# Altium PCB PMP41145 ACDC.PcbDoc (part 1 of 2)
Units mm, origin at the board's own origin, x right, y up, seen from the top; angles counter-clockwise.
Board outline 48.82 x 27.36 mm, 2 copper layers (Top Layer, Bottom Layer), stack 1.016 mm thick; 61 components, 40 nets, 174 pads, 389 vias.
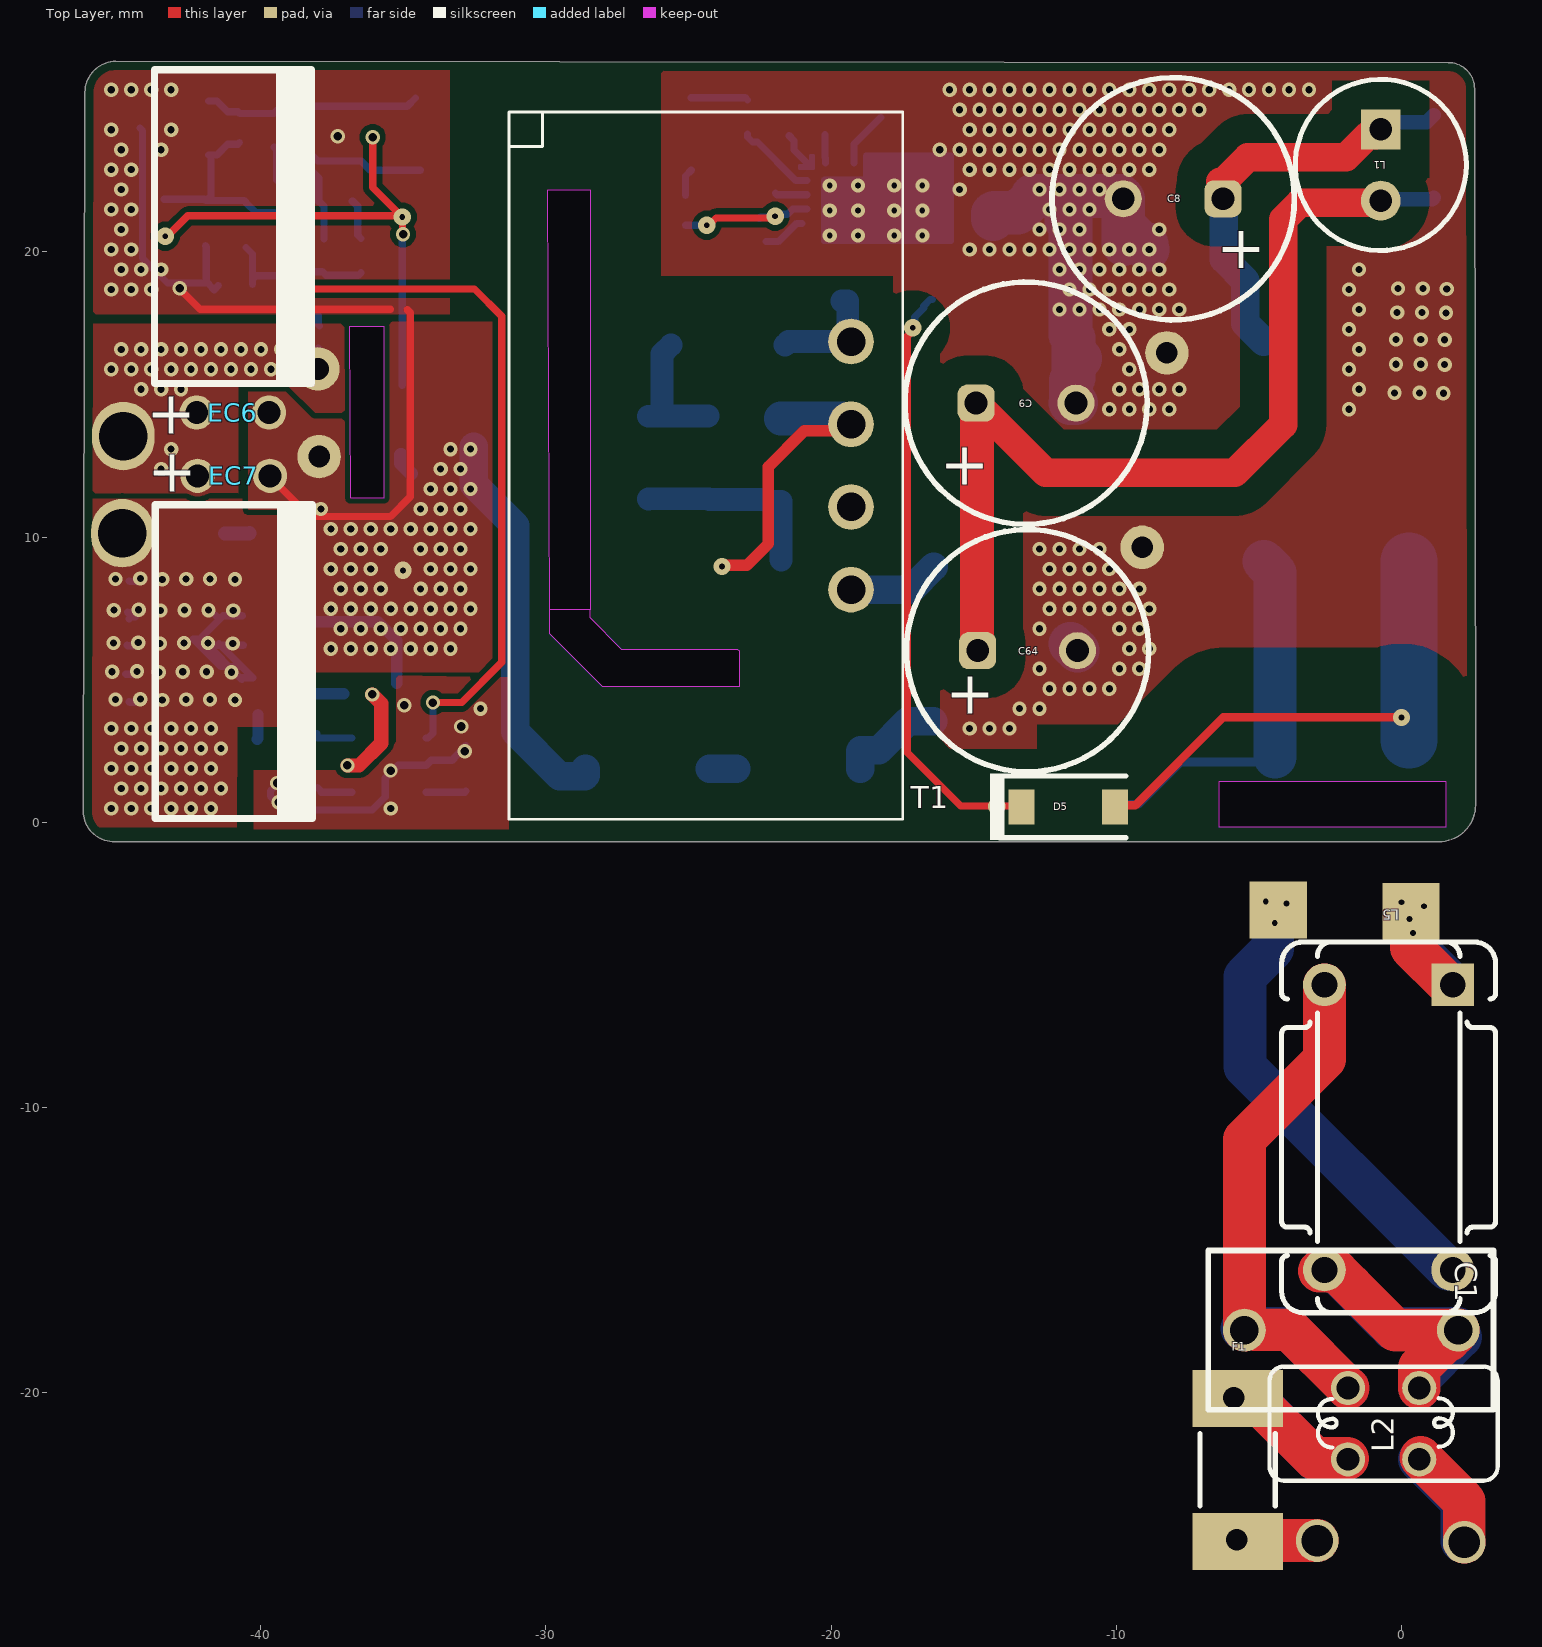
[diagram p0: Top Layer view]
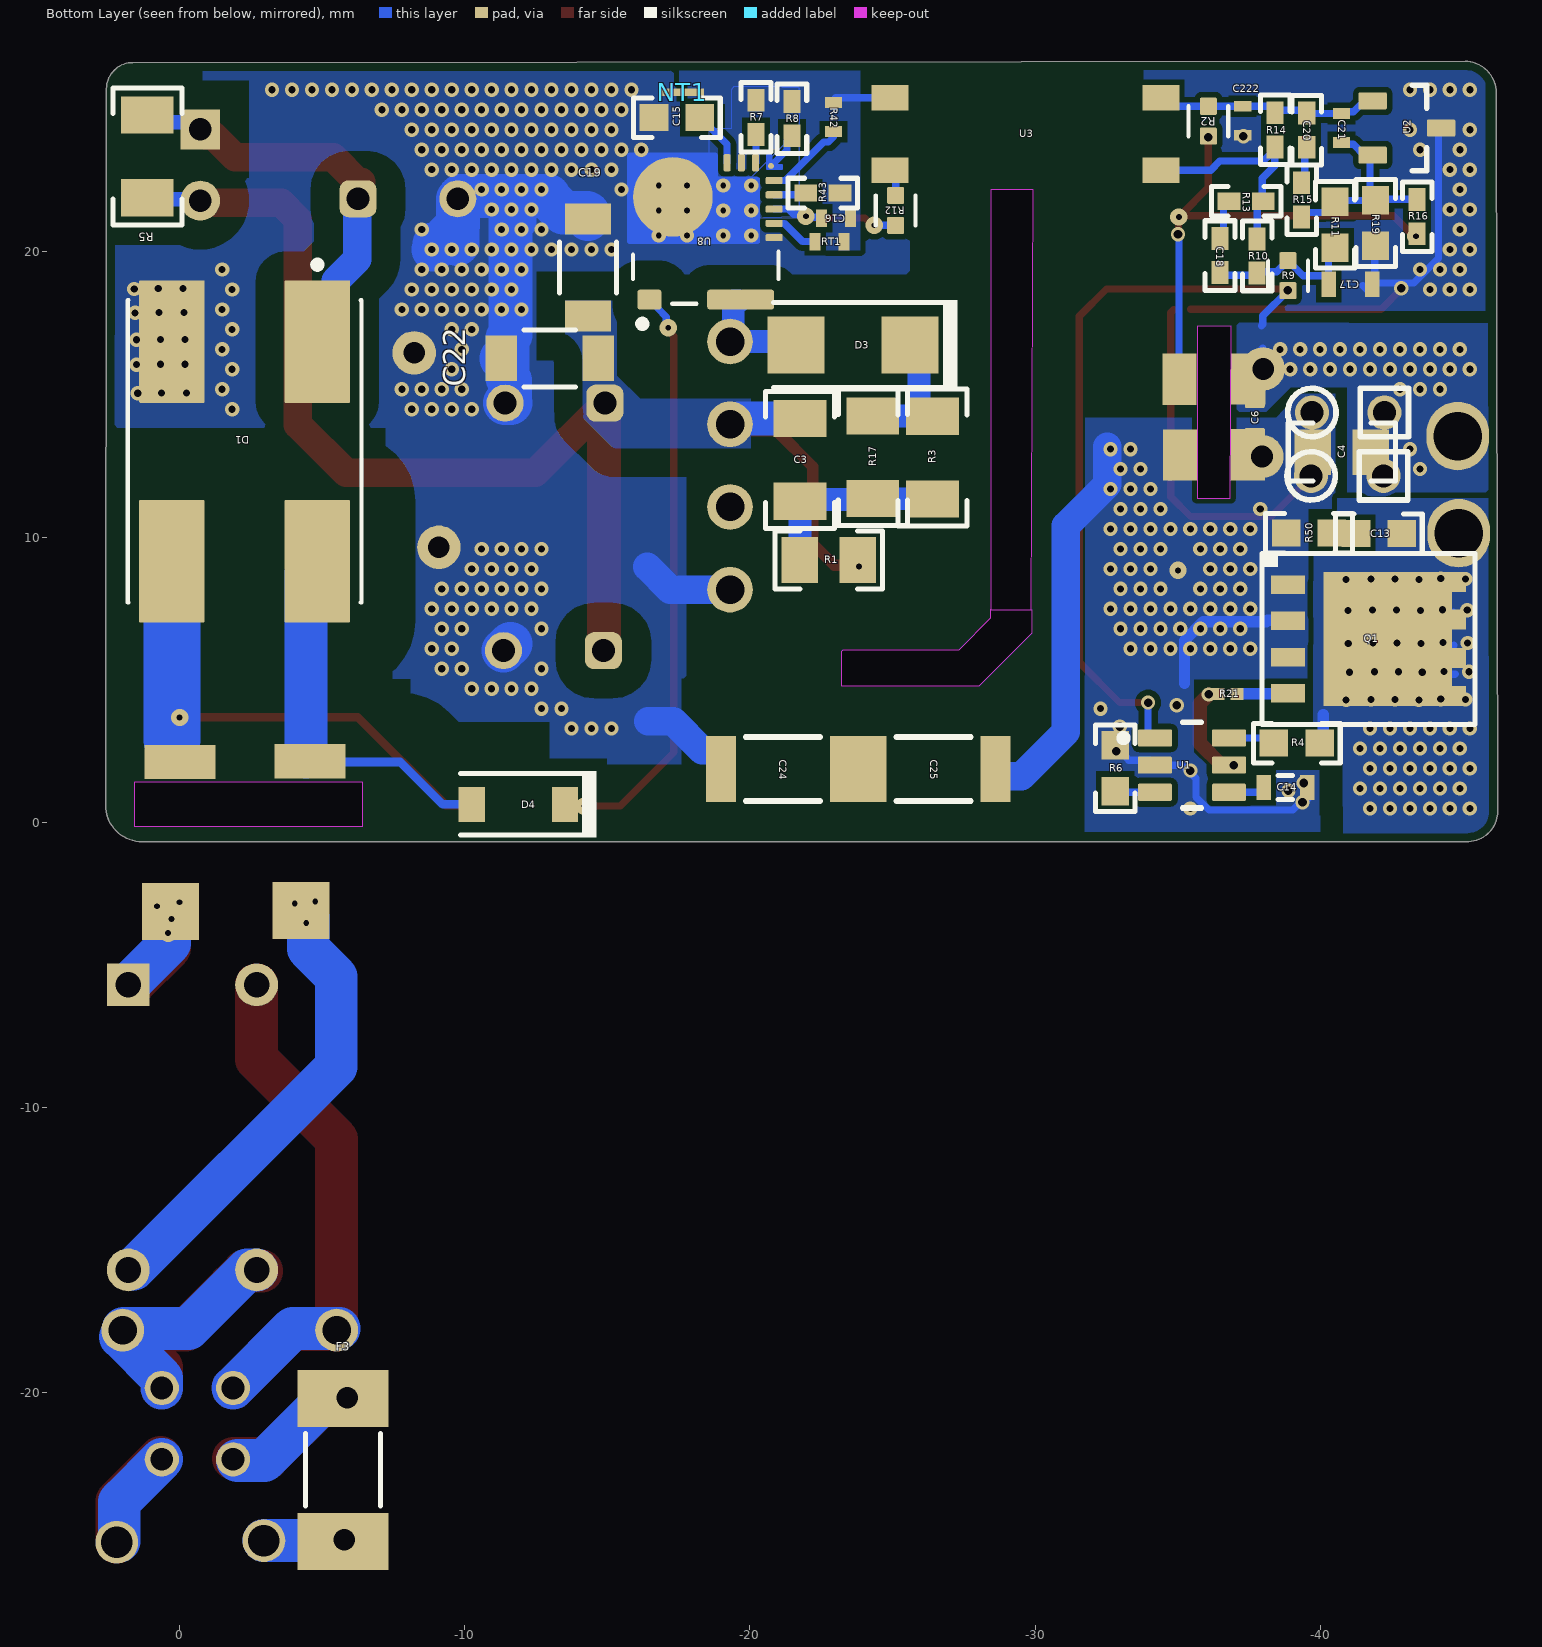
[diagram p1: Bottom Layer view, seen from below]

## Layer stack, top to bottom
Top Solder: solder mask 0.0102, Solder Resist, Dk 3.5
Top Layer: signal copper 0.0711
Dielectric1: core 0.8738, FR-4 High Tg, Dk 4.8
Bottom Layer: signal copper 0.0711
Bottom Solder: solder mask 0.0102, Solder Resist, Dk 3.5

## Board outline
-45.202,-0.676 cw(c-45.155,0.387) -46.208,0.234 -46.219,0.27 -46.164,25.595 cw(c-45.075,25.595) -45.075,26.684 1.643,26.644 cw(c1.643,25.723) 2.564,25.723 2.599,0.602 cw(c1.317,0.602) 1.318,-0.679 1.29,-0.679
cut-out: -6.406,1.425 -6.406,-0.15 1.576,-0.15 1.576,1.425
cut-out: -29.885,7.455 -29.885,6.63 -28.025,4.77 -23.21,4.77 -23.21,6 -23.27,6.06 -27.335,6.06 -28.445,7.17 -28.445,7.47
cut-out: -35.685,11.37 -36.846,11.37 -36.872,17.4 -35.685,17.4
cut-out: -28.445,7.455 -29.869,7.455 -29.931,22.185 -28.445,22.185 -28.445,19.53

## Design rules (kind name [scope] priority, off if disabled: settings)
AcuteAngle [All] p1: minimum=4.50000000000000E+0001 checktracksonly=FALSE
AssemblyTestPointUsage [All] p1: valid=2
BoardOutlineClearance BoardOutlineClearance_MountingHoles [OnCopper and InComponentClass('Mounting Holes')] p1: gap=0.3 ignorepadtopadclearanceinfootprint=FALSE
BoardOutlineClearance BoardOutlineClearance_Poly [OnCopper and IsPoly] p2: gap=0.3 ignorepadtopadclearanceinfootprint=FALSE
BoardOutlineClearance [OnCopper and Not InComponentClass('Logo') and not InComponentClass('FiducialMark') and not InRegion(1000,500,4000,800) and not InPoly] p3: gap=0.3 ignorepadtopadclearanceinfootprint=FALSE
Clearance Clearance_VAC_PGND [InNetClass('VAC') vs InNetClass('PGND')] p1: gap=2.286 ignorepadtopadclearanceinfootprint=TRUE
Clearance Clearance_HV_PGND [InNetClass('High Voltage') vs InNetClass('PGND')] p2: gap=1.016 ignorepadtopadclearanceinfootprint=TRUE
Clearance Clearance_SW_PGND [InNetClass('Switch Node') vs InNetClass('PGND')] p3: gap=0.864 ignorepadtopadclearanceinfootprint=TRUE
Clearance Clearance_AC_AC [InNetClass('VAC') vs InNetClass('VAC')] p4: gap=1 ignorepadtopadclearanceinfootprint=TRUE
Clearance Clearance_PGND_SGND [InNetClass('PGND') vs InNetClass('SGND')] p5: gap=4.064 ignorepadtopadclearanceinfootprint=TRUE
Clearance Clearance_HV_LV [InNetClass('High Voltage') vs InNetClass('Low Voltage')] p6: gap=0.864 ignorepadtopadclearanceinfootprint=TRUE
Clearance Clearance_SW_LV_1 [InNetClass('Switch Node') vs InNetClass('Low Voltage')] p7: gap=0.864 ignorepadtopadclearanceinfootprint=TRUE
Clearance Clearance_SW_HV [InNetClass('Switch Node') vs InNetClass('High Voltage')] p8: gap=0.864 ignorepadtopadclearanceinfootprint=TRUE
Clearance Clearance_1 [All] p9: gap=0.198 ignorepadtopadclearanceinfootprint=TRUE
Clearance Clearance_Keepouts [((IsTrack Or IsArc) And Not InPoly) And IsFree and IsKeepOut vs ((IsTrack Or IsArc) And Not InPoly) And IsFree and IsKeepOut] p10: gap=0 ignorepadtopadclearanceinfootprint=FALSE
Clearance Clearance_Poly [InPolygon] p11: gap=0.254 ignorepadtopadclearanceinfootprint=TRUE
Clearance Clearance_FiducialMark [IsKeepOut and InComponentClass('FiducialMark') vs IsPad and InComponentClass('FiducialMark')] p12: gap=0 ignorepadtopadclearanceinfootprint=FALSE
ComponentClearance ComponentClearance_MountingHoles_FiducialMarks [InComponentClass('Mounting Holes') vs InComponentClass('FiducialMark')] p1: gap=0.2 collisioncheckmode=3 verticalgap=0.2 showdistances=FALSE
ComponentClearance ComponentClearance_Shunt [InComponentClass('Header') vs InComponentClass('Shunt')] p2: gap=0 collisioncheckmode=3 verticalgap=0 showdistances=FALSE
ComponentClearance ComponentClearance_Logo [InComponentClass('Logo')] p3: gap=0.2 collisioncheckmode=3 verticalgap=0.2 showdistances=FALSE
ComponentClearance ComponentClearance_ScrewToNut [(HasFootprint('NY PMS 440 0025 PH')) vs (HasFootprint('Keystone_1902C'))] p4: gap=0.127 collisioncheckmode=3 verticalgap=0.254 showdistances=FALSE
ComponentClearance ComponentClearance_MountingHoles [InComponentClass('Mounting Holes')] p5: gap=1 collisioncheckmode=3 verticalgap=2540 showdistances=FALSE
ComponentClearance ComponentClearance_SmallPassives [HasFootprint('0201*') or HasFootprint('0402*') or HasFootprint('0508') or HasFootprint('0603*') or HasFootprint('0612') or HasFootprint('0805*') or HasFootprint('0815*') or HasFootprint('0830*') or HasFootprint('1206*') or HasFootprint('1210*') or HasFootprint('1808*') or HasFootprint('1812*') or HasFootprint('1825*') or HasFootprint('2010*') or HasFootprint('2220*') or HasFootprint('2225*') or HasFootprint('2512*') or HasFootprint('2728*') or HasFootprint('3518*') vs HasFootprint('0201*') or HasFootprint('0402*') or HasFootprint('0508') or HasFootprint('0603*') or HasFootprint('0612') or HasFootprint('0805*') or HasFootprint('0815*') or HasFootprint('0830*') or HasFootprint('1206*') or HasFootprint('1210*') or HasFootprint('1808*') or HasFootprint('1812*') or HasFootprint('1825*') or HasFootprint('2010*') or HasFootprint('2220*') or HasFootprint('2225*') or HasFootprint('2512*') or HasFootprint('2728*') or HasFootprint('3518*')] p6: gap=0.2 collisioncheckmode=3 verticalgap=0.2 showdistances=FALSE
ComponentClearance ComponentClearance_THtoSMT [IsThruComponent vs IsSMTComponent] p7: gap=0.2 collisioncheckmode=3 verticalgap=0.2 showdistances=FALSE
ComponentClearance ComponentClearance_THtoTH [IsThruComponent vs IsThruComponent] p8: gap=0.2 collisioncheckmode=3 verticalgap=0.2 showdistances=FALSE
ComponentClearance [All] p9: gap=0.1 collisioncheckmode=3 verticalgap=0.1 showdistances=FALSE
DiffPairsRouting DiffPair_DiffPairsRouting [All] p1: maxlimit=0.254 minlimit=0.254 mostfreqgap=0.254 toplayer_minwidth=0.254 toplayer_maxwidth=0.254 toplayer_prefwidth=0.254 bottomlayer_minwidth=0.254 bottomlayer_maxwidth=0.254 bottomlayer_prefwidth=0.254 filterlayerstackid={9F2BDCAB-BF4A-4FAE-9F57-695CEC5DA6CF} maxuncoupledlength=12.7
DiffPairsRouting DiffPair_DiffPairsRouting_1 [InDifferentialPair ('NewDifferentialPair1')] p2: maxlimit=0.203 minlimit=0.203 mostfreqgap=0.203 toplayer_minwidth=0.254 toplayer_maxwidth=0.254 toplayer_prefwidth=0.254 bottomlayer_minwidth=0.254 bottomlayer_maxwidth=0.254 bottomlayer_prefwidth=0.254 filterlayerstackid={9F2BDCAB-BF4A-4FAE-9F57-695CEC5DA6CF} maxuncoupledlength=12.7
DiffPairsRouting DiffPair_DiffPairsRouting_2 [InDifferentialPair ('NewDifferentialPair1')] p3: maxlimit=0.127 minlimit=0.127 mostfreqgap=0.127 toplayer_minwidth=0.254 toplayer_maxwidth=0.254 toplayer_prefwidth=0.254 bottomlayer_minwidth=0.254 bottomlayer_maxwidth=0.254 bottomlayer_prefwidth=0.254 filterlayerstackid={9F2BDCAB-BF4A-4FAE-9F57-695CEC5DA6CF} maxuncoupledlength=12.7
DiffPairsRouting DiffPair_DiffPairsRouting_3 [InDifferentialPair ('NewDifferentialPair1')] p4: maxlimit=0.178 minlimit=0.178 mostfreqgap=0.178 toplayer_minwidth=0.254 toplayer_maxwidth=0.254 toplayer_prefwidth=0.254 bottomlayer_minwidth=0.254 bottomlayer_maxwidth=0.254 bottomlayer_prefwidth=0.254 filterlayerstackid={9F2BDCAB-BF4A-4FAE-9F57-695CEC5DA6CF} maxuncoupledlength=12.7
DiffPairsRouting DiffPair_DiffPairsRouting_4 [InDifferentialPair ('NewDifferentialPair1')] p5: maxlimit=0.254 minlimit=0.254 mostfreqgap=0.254 toplayer_minwidth=0.381 toplayer_maxwidth=0.381 toplayer_prefwidth=0.381 bottomlayer_minwidth=0.381 bottomlayer_maxwidth=0.381 bottomlayer_prefwidth=0.381 filterlayerstackid={9F2BDCAB-BF4A-4FAE-9F57-695CEC5DA6CF} maxuncoupledlength=12.7
DiffPairsRouting DiffPair_DiffPairsRouting_5 [All] p6: maxlimit=0.254 minlimit=0.254 mostfreqgap=0.254 toplayer_minwidth=0.254 toplayer_maxwidth=0.254 toplayer_prefwidth=0.254 bottomlayer_minwidth=0.254 bottomlayer_maxwidth=0.254 bottomlayer_prefwidth=0.254 filterlayerstackid={9F2BDCAB-BF4A-4FAE-9F57-695CEC5DA6CF} maxuncoupledlength=12.7
DiffPairsRouting DiffPair_DiffPairsRouting_6 [All] p7: maxlimit=0.254 minlimit=0.254 mostfreqgap=0.254 toplayer_minwidth=0.254 toplayer_maxwidth=0.254 toplayer_prefwidth=0.254 bottomlayer_minwidth=0.254 bottomlayer_maxwidth=0.254 bottomlayer_prefwidth=0.254 filterlayerstackid={9F2BDCAB-BF4A-4FAE-9F57-695CEC5DA6CF} maxuncoupledlength=12.7
DiffPairsRouting DiffPair_DiffPairsRouting_7 [InDifferentialPair ('NewDifferentialPair2')] p8: maxlimit=0.254 minlimit=0.254 mostfreqgap=0.254 toplayer_minwidth=0.254 toplayer_maxwidth=0.254 toplayer_prefwidth=0.254 bottomlayer_minwidth=0.254 bottomlayer_maxwidth=0.254 bottomlayer_prefwidth=0.254 filterlayerstackid={9F2BDCAB-BF4A-4FAE-9F57-695CEC5DA6CF} maxuncoupledlength=12.7
DiffPairsRouting DiffPair_DiffPairsRouting_8 [InDifferentialPair ('NewDifferentialPair2')] p9: maxlimit=0.254 minlimit=0.254 mostfreqgap=0.254 toplayer_minwidth=0.381 toplayer_maxwidth=0.381 toplayer_prefwidth=0.381 bottomlayer_minwidth=0.381 bottomlayer_maxwidth=0.381 bottomlayer_prefwidth=0.381 filterlayerstackid={9F2BDCAB-BF4A-4FAE-9F57-695CEC5DA6CF} maxuncoupledlength=12.7
DiffPairsRouting DiffPair_DiffPairsRouting_9 [InDifferentialPair ('ISense_A')] p10: maxlimit=0.198 minlimit=0.198 mostfreqgap=0.198 toplayer_minwidth=0.254 toplayer_maxwidth=0.254 toplayer_prefwidth=0.254 bottomlayer_minwidth=0.254 bottomlayer_maxwidth=0.254 bottomlayer_prefwidth=0.254 filterlayerstackid={9F2BDCAB-BF4A-4FAE-9F57-695CEC5DA6CF} maxuncoupledlength=12.7
DiffPairsRouting DiffPair_DiffPairsRouting_10 [InDifferentialPair ('ISense_A')] p11: maxlimit=0.254 minlimit=0.254 mostfreqgap=0.254 toplayer_minwidth=0.381 toplayer_maxwidth=0.381 toplayer_prefwidth=0.381 bottomlayer_minwidth=0.381 bottomlayer_maxwidth=0.381 bottomlayer_prefwidth=0.381 filterlayerstackid={9F2BDCAB-BF4A-4FAE-9F57-695CEC5DA6CF} maxuncoupledlength=12.7
DiffPairsRouting DiffPair_DiffPairsRouting_11 [InDifferentialPair ('ISense_A')] p12: maxlimit=0.254 minlimit=0.254 mostfreqgap=0.254 toplayer_minwidth=0.381 toplayer_maxwidth=0.381 toplayer_prefwidth=0.381 bottomlayer_minwidth=0.381 bottomlayer_maxwidth=0.381 bottomlayer_prefwidth=0.381 filterlayerstackid={9F2BDCAB-BF4A-4FAE-9F57-695CEC5DA6CF} maxuncoupledlength=12.7
DiffPairsRouting DiffPair_ADiffPairsRouting [All] p13: maxlimit=0.198 minlimit=0.198 mostfreqgap=0.198 toplayer_minwidth=0.254 toplayer_maxwidth=0.254 toplayer_prefwidth=0.254 bottomlayer_minwidth=0.254 bottomlayer_maxwidth=0.254 bottomlayer_prefwidth=0.254 filterlayerstackid={9F2BDCAB-BF4A-4FAE-9F57-695CEC5DA6CF} maxuncoupledlength=12.7
DiffPairsRouting [All] p14: maxlimit=2.54 minlimit=0.254 mostfreqgap=0.254 toplayer_minwidth=0.381 toplayer_maxwidth=0.381 toplayer_prefwidth=0.381 bottomlayer_minwidth=0.381 bottomlayer_maxwidth=0.381 bottomlayer_prefwidth=0.381 maxuncoupledlength=25.4
FabricationTestPointUsage TestPointUsage [All] p1: valid=2 allowmultiple=FALSE
FabricationTestpoint Testpoint [All] p1: side=3 testpointundercomponent=TRUE minsize=1.016 maxsize=2.54 preferedsize=1.524 minholesize=0 maxholesize=1.016 preferedholesize=0.813 testpointgrid=0.025 allowsidetop=TRUE allowsidebottom=TRUE usegrid=TRUE gridtolerance=0
FanoutControl Fanout_LCC [IsLCC] p1: bgadir=Out bgaviamode=Centered fanoutstyle=Auto fanoutdirection=Alternating viagrid=0.025 // Fanout_LCC (Default Rule)
FanoutControl Fanout_BGA [IsBGA] p2: bgadir=Out bgaviamode=Centered fanoutstyle=Auto fanoutdirection=Alternating viagrid=0.025 // Fanout_BGA (Default Rule)
HoleSize [All] p1: absolutevalues=TRUE maxlimit=6.375 minlimit=0.2 maxpercent=80.000 minpercent=20.000
MatchedLengths DiffPair_MatchedLengths [All] p1: tolerance=25.4 checknetsindiffpair=FALSE checkdiffpairvsdiffpair=TRUE checkxsignals=TRUE checkothers=TRUE
MatchedLengths DiffPair_MatchedLengths_1 [InDifferentialPair ('NewDifferentialPair1')] p2: tolerance=25.4 checknetsindiffpair=FALSE checkdiffpairvsdiffpair=TRUE checkxsignals=TRUE checkothers=TRUE
MatchedLengths DiffPair_MatchedLengths_2 [InDifferentialPair ('NewDifferentialPair1')] p3: tolerance=25.4 checknetsindiffpair=FALSE checkdiffpairvsdiffpair=TRUE checkxsignals=TRUE checkothers=TRUE
MatchedLengths DiffPair_MatchedLengths_3 [InDifferentialPair ('NewDifferentialPair1')] p4: tolerance=25.4 checknetsindiffpair=FALSE checkdiffpairvsdiffpair=TRUE checkxsignals=TRUE checkothers=TRUE
MatchedLengths DiffPair_MatchedLengths_4 [InDifferentialPair ('NewDifferentialPair1')] p5: tolerance=25.4 checknetsindiffpair=FALSE checkdiffpairvsdiffpair=TRUE checkxsignals=TRUE checkothers=TRUE
MatchedLengths DiffPair_MatchedLengths_5 [All] p6: tolerance=25.4 checknetsindiffpair=FALSE checkdiffpairvsdiffpair=TRUE checkxsignals=TRUE checkothers=TRUE
MatchedLengths DiffPair_MatchedLengths_6 [All] p7: tolerance=25.4 checknetsindiffpair=FALSE checkdiffpairvsdiffpair=TRUE checkxsignals=TRUE checkothers=TRUE
MatchedLengths DiffPair_MatchedLengths_7 [InDifferentialPair ('NewDifferentialPair2')] p8: tolerance=25.4 checknetsindiffpair=FALSE checkdiffpairvsdiffpair=TRUE checkxsignals=TRUE checkothers=TRUE
MatchedLengths DiffPair_MatchedLengths_8 [InDifferentialPair ('NewDifferentialPair2')] p9: tolerance=25.4 checknetsindiffpair=FALSE checkdiffpairvsdiffpair=TRUE checkxsignals=TRUE checkothers=TRUE
MatchedLengths DiffPair_MatchedLengths_9 [InDifferentialPair ('ISense_A')] p10: tolerance=25.4 checknetsindiffpair=FALSE checkdiffpairvsdiffpair=TRUE checkxsignals=TRUE checkothers=TRUE
MatchedLengths DiffPair_MatchedLengths_10 [InDifferentialPair ('ISense_A')] p11: tolerance=25.4 checknetsindiffpair=FALSE checkdiffpairvsdiffpair=TRUE checkxsignals=TRUE checkothers=TRUE
MatchedLengths DiffPair_MatchedLengths_11 [InDifferentialPair ('ISense_A')] p12: tolerance=25.4 checknetsindiffpair=FALSE checkdiffpairvsdiffpair=TRUE checkxsignals=TRUE checkothers=TRUE
MatchedLengths DiffPair_AMatchedLengths [All] p13: tolerance=25.4 checknetsindiffpair=FALSE checkdiffpairvsdiffpair=TRUE checkxsignals=TRUE checkothers=TRUE
MinimumAnnularRing MinimumAnnularRing_ThermalPadVias [IsVia and InAnyComponent] p1: minimumring=0.15
MinimumAnnularRing [All] p2: minimumring=0.2
MinimumSolderMaskSliver MinimumSolderMaskSliver_Logo [InComponentClass('Logo') vs InComponentClass('Logo')] p1: minsoldermaskwidth=0.018
MinimumSolderMaskSliver [All] p2: minsoldermaskwidth=0.1
PlaneConnect [All] p1: planeconnectstyle=Relief reliefexpansion=0.254 reliefentries=4 reliefconductorwidth=0.254 reliefairgap=0.254
PolygonConnect [All] p1: connectstyle=Direct reliefconductorwidth=0.254 reliefentries=4 polygonreliefangle="90 Angle" airgapwidth=0
RoutingVias ThermalPadVias [IsVia and InAnyComponent] p1: holewidth=0.2 width=0.5 viastyle="Through Hole" minholewidth=0.2 minwidth=0.5 maxholewidth=0.33 maxwidth=0.6
RoutingVias [All] p2: holewidth=0.406 width=0.864 viastyle="Through Hole" minholewidth=0.2 minwidth=0.61 maxholewidth=1.016 maxwidth=1.651
SilkToSilkClearance SilkToSilkClearance_Pb-FreeLogo [(HasFootprint('Pb-Free_Overlay_Medium') OR HasFootprint('Pb-Free_Overlay_Small')) vs (HasFootprint('Pb-Free_Overlay_Medium') OR HasFootprint('Pb-Free_Overlay_Small'))] p1: silktosilkclearance=0
SilkToSilkClearance [All] p2: silktosilkclearance=0.1
SilkToSolderMaskClearance SilkToComponentPadClearance [(IsPad or IsFill or IsRegion) and InAnycomponent] p1: minsilkscreentomaskgap=0.127 clearancetoexposedcopper=TRUE
SilkToSolderMaskClearance "Silk to Solder Mask Opening" [All] p2: minsilkscreentomaskgap=0.1 clearancetoexposedcopper=FALSE
SolderMaskExpansion [All] p1: expansion=0.05 istentingtop=FALSE
UnRoutedNet [All] p1: checkbadconnections=TRUE
Width [All] p1: maxlimit=2.54 minlimit=0.152 preferedwidth=0.254 checkconnectedcopper=TRUE
17 further rules are at their usual default settings.

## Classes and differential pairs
net class "Low Voltage": APGND FB_ACDC NetC15_1 NetC16_1 NetC17_2 NetC18_2 NetC20_1 NetC20_2 NetC21_1 NetD3_2 NetD4_1 NetR7_2 NetR8_2 NetR10_1 NetR12_2 NetR42_2 NetR43_2 NetRT1_2 NetU2_2 NetU2_8 NetU2_9 NetU2_16 NetU2_17 NetU2_18 NetU2_19 NetU2_20 NetU2_21 NetU7_8 PGND SGND VO_ACDC
net class VAC: LINE NetC1_1 NetC1_2 NetD1_2 NetD1_3 Neture
net class "Switch Node": NetD3_2
net class SGND: SGND VO_ACDC VSR_SW
net class PGND: PGND
net class "High Voltage": NetC3_2 NetC8_1 NetD4_1
component class "ACDC Low Side": C3 C4 C6 C8 C9 C13 C14 C15 C16 C17 C18 C19 C20 C21 C22 C24 C25 C64 C222 D1 D3 D4 D5 EC6 EC7 L1 NT1 Q1 R1 R2 R3 R4 R5 R6 R7 R8 R9 R10 R11 R12 R13 R14 R15 R16 R17 R19 R21 R42 R43 R50 RT1 T1 U1 U2 U3 U8

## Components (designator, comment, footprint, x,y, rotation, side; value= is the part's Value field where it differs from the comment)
C1 "890324023028" "X CAP small form 7_10_8" -5.505,-17.805 r0 top
C3 "GRM31BR72J102KW01L" 1206 -21.758,12.71 r90 bottom value=1000pF
C4 "TMK212BBJ106KG-T" 0805_HV -40.753,12.982 r0 bottom value=10uF
C6 "CGA3E2X8R1E104K080AD" FP-CGA3E2X8R1E104K080AD_0603-MFG -37.701,14.178 r270 bottom value=100nF
C8 "33u/400V" WCAP-ATG5_D8H16 -8.005,21.865 r0 top value=33uF
C9 "33u/400V" WCAP-ATG5_D8H16 -13.163,14.699 r180 top value=33uF
C13 "GRM1885C2A221JA01D" 0603 -42.05,10.125 r0 bottom value=220pF
C14 "CGA3E1X7R1E105K080AC" 0603S -38.771,1.223 r180 bottom value=1uF
C15 "GRM188R61E106KA73D" 0603 -17.435,24.712 r0 bottom value=10uF
C16 "GRM155R71H331KA01D" 0402S -23.018,21.186 r180 bottom value=330pF
C17 "C1608X7R1E105K080AB" 0603S -41.052,18.87 r0 bottom value=1uF
C18 "GRM155R71H183KA12D" 0402 -36.48,19.875 r90 bottom value=0.018uF
C19 "C3216X7T2W104M160AA" 1206_180 -14.32,19.455 r90 bottom value=0.1uF
C20 "GRM155R71H472KA01D" 0402 -39.525,24.27 r90 bottom value=4700pF
C21 "885012205055" 0402S -40.74,24.345 r90 bottom value=100pF
C22 "C3216X7T2W104M160AA" 1206_180 -12.977,16.269 r0 bottom value=0.1uF
C24 "885362210009" WCAP-CSSA_1808_L4.5W2H1.6 -21.156,1.871 r180 bottom value=470pF
C25 "885362210009" WCAP-CSSA_1808_L4.5W2H1.6 -26.436,1.871 r180 bottom value=470pF
C64 "33u/400V" WCAP-ATG5_D8H16 -13.109,6.021 r180 top value=33uF
C222 "885012205055" 0402S -37.275,24.6 r90 bottom value=100pF
D1 "Z4DGP406L-HF" FP-Z4DGP406L-HF_SMT_8MM1_10MM5-MFG -2.28,13.005 r180 bottom
D3 "MRA4007T3G" SMA -23.614,16.74 r0 bottom value=1000V
D4 "ES1JFL" SOD-123 -11.88,0.63 r0 bottom value=600V
D5 "ES1JFL" SOD-123 -11.685,0.54 r0 top value=600V
EC6 "ECAP_LAYDOWN" CE05.5P254L11 -42.245,14.37 r0 top value=470uF
EC7 "ECAP_LAYDOWN" CE05.5P254L11 -42.215,12.15 r0 top value=470uF
F1 "SSQ 3" FUSE_SSQ -5.745,-22.71 r90 top
F3 "SSQ 3" FUSE_SSQ -5.73,-22.71 r90 bottom
L1 "7447462220" WE-TI_5075 -0.725,23.051 r270 top value=22uH
L2 "" L-T8*5 -0.647,-21.088 r180 top
L5 "744821201" WE-CMB_XS -0.45,-10.695 r270 top value=1mH
NT1 "Net-Tie" Net-Tie_10milWide_30milLong -17.621,25.599 r180 bottom net-tie
Q1 "BSC093N15NS5ATMA1" PG-TDSON-8 -41.69,6.43 r180 bottom value=150V
R1 "CRCW0805470KJNEA" 0805_HV -22.763,9.201 r180 bottom value=470k
R2 "CRCW04020000Z0EDHP" FP-CRCW04020000Z0EDHP_0402-MFG -36.075,24.585 r90 bottom value=0
R3 "RC1206FR-0730RL" 1206 -26.401,12.789 r270 bottom value=30.0
R4 "RC0603FR-07300RL" 0603 -39.174,2.777 r0 bottom value=300
R5 "CRCW12064K70JNEA" 1206 1.133,23.352 r270 bottom value=4.7k
R6 "CRCW060347K0FKEA" 0603 -32.807,1.897 r270 bottom value=47.0k
R7 "CRCW040228K7FKED" 0402 -20.21,24.72 r270 bottom value=28.7k
R8 "CRCW040228K7FKED" 0402 -21.47,24.675 r270 bottom value=28.7k
R9 "CRCW04020000Z0EDHP" FP-CRCW04020000Z0EDHP_0402-MFG -38.865,19.17 r270 bottom value=0
R10 "CRCW04023K01FKED" 0402 -37.785,19.86 r270 bottom value=3.01k
R11 "RC0603FR-07232KL" 0603 -40.515,20.955 r270 bottom value=232k
R12 "CRCW04020000Z0EDHP" FP-CRCW04020000Z0EDHP_0402-MFG -25.108,21.457 r90 bottom value=0
R13 "CRCW0402150RFKED" 0402 -37.395,21.78 r0 bottom value=150
R14 "CRCW040215K0FKED" 0402 -38.415,24.285 r270 bottom value=15.0k
R15 "RC0402FR-074K7L" 0402 -39.345,21.825 r270 bottom value=4.70k
R16 "CRCW04021R00JNED" 0402 -43.395,21.24 r270 bottom value=1.0
R17 "RC1206FR-0730RL" 1206 -24.306,12.805 r270 bottom value=30.0
R19 "CRCW060333K0FKEA" 0603 -41.94,21.015 r90 bottom value=33.0k
R21 "CRCW02010000Z0ED" 0201 -36.745,4.505 r0 bottom value=0
R42 "CRCW040275K0FKED" 0402S -22.93,24.728 r270 bottom value=75.0k
R43 "CRCW04025K23FKED" 0402 -22.553,22.065 r0 bottom value=5.23k
R50 "CRCW060312R0JNEA" 0603 -39.6,10.14 r180 bottom value=12
RT1 "NCP15WF104F03RC" 0402S -22.792,20.363 r0 bottom value=100k
T1 "ATQ23_14 4_4 Pin" "ATQ23.9_13.8_REMOVE FLYWIRE" -19.3,12.51 r0 top
U1 "MP6908GJ-Z" FP-MP6908GJ-Z_TSOT23-6-MFG -35.498,2.005 r180 bottom
U2 "ATL431AIDBZR" DBZ0003A_N -43.033,24.346 r180 bottom
U3 "VOL618A-2T" SOP254P1020X230-4 -29.655,24.14 r0 bottom
U8 "UCG28826" REZ0012A-MFG -18.448,20.73 r90 bottom

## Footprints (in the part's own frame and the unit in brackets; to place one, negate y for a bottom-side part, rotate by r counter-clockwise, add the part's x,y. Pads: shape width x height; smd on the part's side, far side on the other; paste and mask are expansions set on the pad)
0201 [mm] "Data from Kemet datasheet CC101_COM dated 7/28/11"
  rect 0.46x0.42 smd mask+0.048: 1(-0.33,0) 2(0.33,0)
  body extent -0.31,-0.16 0.31,0.16, height 0.26
0402 [mm] "0402 from SM-752 data"
  rect 0.8x0.6 smd: 1(-0.6,0) 2(0.6,0)
  silkscreen extent -1.22,-0.52 1.22,0.52, body extent -0.55,-0.3 0.55,0.3, height 0.6
0402S [mil] "Based on C0402S footprint from PADS legacy"
  rect 15x24 smd: 1(-20,0) 2(20,0)
  body extent -22,-12 22,12, height 24
0603 [mm] "0603 from SM-752 data"
  rect 1x0.95 smd: 1(-0.8,0) 2(0.8,0)
  silkscreen extent -1.52,-0.69 1.52,0.69, body extent -0.87,-0.47 0.87,0.47, height 1
0603S [mil]
  rect 20x35 smd: 1(-30,0) 2(30,0)
  silkscreen extent -10,-17 10,17, body extent -34,-19 34,19, height 39
0805_HV [mil] "0805 with 30mil clearance between pads"
  rect 50x63 smd: 1(-40,0) 2(40,0)
  silkscreen extent -74,-40 74,40, body extent -43,-29 43,29, height 57
1206 [mm] "1206 from SM-752 data"
  rect 1.3x1.85 smd: 1(-1.45,0) 2(1.45,0)
  silkscreen extent -2.4,-1.21 2.4,1.21, body extent -1.7,-0.9 1.7,0.9, height 1.35
1206_180 [mm] "1206_180"
  rect 1.1x1.6 smd: 1(-1.7,0) 2(1.7,0)
  silkscreen extent -0.9,-1 0.9,1, body extent -1.75,-0.95 1.75,0.95, height 1.8
"ATQ23.9_13.8_REMOVE FLYWIRE" [mm]
  round 1.6 hole 1: 1(0,-4.35) 2(0,-1.45) 3(0,1.45) 4(0,4.35)
  silkscreen extent -11.99,-12.4 1.81,12.4
CE05.5P254L11 [mm]
  round 1.2 hole 0.8: 1(0,0) 2(2.54,0)
  silkscreen extent -1.48,1.02 4.02,12.02
DBZ0003A_N [mm] "SOT23, 3-Leads, Body 2.9x1.3mm, Pitch 0.95mm, Lead Span 2.4mm, IPC Medium Density"
  rrect17% 1x0.6 smd: 1(-1.2,0.95) 2(-1.2,-0.95) 3(1.2,0)
  silkscreen extent 0.2,-1.5 0.7,1.5, body extent -1.26,-1.46 1.26,1.46, height 0.98
FP-CGA3E2X8R1E104K080AD_0603-MFG [mm]
  rrect14% 0.7x0.7 smd paste+0 mask+0: 1(-0.7,0) 2(0.7,0)
  body extent -0.8,-0.4 0.8,0.4, height 0.95
FP-CRCW04020000Z0EDHP_0402-MFG [mm]
  rrect17% 0.6x0.6 smd paste+0 mask+0: 1(-0.525,0) 2(0.525,0)
  silkscreen extent -0.53,-0.7 0.53,0.7, body extent -0.5,-0.25 0.5,0.25, height 0.4
FP-MP6908GJ-Z_TSOT23-6-MFG [mm]
  rrect17% 1.2x0.6 smd paste+0 mask+0: 1(-1.3,0.95) 2(-1.3,0) 3(-1.3,-0.95) 4(1.3,-0.95) 5(1.3,0) 6(1.3,0.95)
  silkscreen extent -2.53,-1.5 0.33,1.5, body extent -1.4,-1.45 1.4,1.45, height 1
FP-Z4DGP406L-HF_SMT_8MM1_10MM5-MFG [mm]
  rrect4% 2.3x4.3 smd paste+0 mask+0: 1(2.55,3.85) 2(2.55,-3.85) 3(-2.55,-3.85) 4(-2.55,3.85)
  silkscreen extent -4.1,-5.3 4.1,6.67, body extent -4.05,-5.25 4.05,5.25, height 1.45
FUSE_SSQ [mm] "Bel Fuse"
  rect 2x3.18 smd: 1(-2.5,0) 2(2.5,0)
  silkscreen extent -1.27,-1.32 1.27,1.32, body extent -3.17,-1.32 3.17,1.32, height 2.64
L-T8*5 [mm]
  round 1.2 hole 0.8: 1(-1.272,-1.253) 2(1.228,-1.253) 3(1.228,1.247) 4(-1.272,1.247)
  silkscreen extent -4.02,-2 3.98,2, body extent -4.9,-2.9 5.1,3.1, height 10
Net-Tie_10milWide_30milLong [mil] "10mil net tie, no solder mask opening, no solder paste"
  rect 30x10 smd paste-5 mask-5: 1(-15,0) 2(15,0)
PG-TDSON-8 [mm] "Infineon recommended land pattern"
  rect 1.2x0.65 smd: 1(-2.825,1.905) 2(-2.825,0.635) 3(-2.825,-0.635) 4(-2.825,-1.905)
  rect 0.5x0.7 smd: 5(3.175,-2) 6(3.175,-0.675) 7(3.175,0.675) 8(3.175,2)
  rect 4.5x4.7 smd paste-2.25: 9(0.675,0)
  silkscreen extent -3.74,-3 3.74,3, body extent -3.18,-2.89 3.18,2.9, height 1.1
REZ0012A-MFG [mm]
  rrect29% 0.7x0.85 smd paste-1000 mask-1000: 1(-2.4,1.975)
  rrect29% 0.7x2.35 smd paste-1000 mask-1000: 2(-2.4,-1.225)
  rrect40% 0.25x0.6 smd paste+0 mask+0: 3(-0.225,-2.4) 4(0.275,-2.4) 5(0.775,-2.4) 6(1.275,-2.4) 7(1.775,-2.4)
  round 0.203 smd paste+0 mask+0: 8(2.288,-2.288)
  rrect40% 0.6x0.25 smd paste+0 mask+0: 9(2.4,-1.75) 10(2.4,-1.25) 11(2.4,-0.75)
  round 2.788 smd paste-1000 mask-1000: 12(1.199,1.148)
  Top Layer region: 2.2,-2.7 2.175,-2.693 2.157,-2.675 2.15,-2.65 2.15,-2.65 2.15,-2.175 2.154,-2.156 2.165,-2.14 2.181,-2.129 2.2,-2.125 2.2,-2.125 2.65,-2.125 2.669,-2.129 2.685,-2.14 2.696,-2.156 2.7,-2.175 2.7,-2.175 2.7,-2.275 2.693,-2.3 2.675,-2.318 2.65,-2.325 2.65,-2.325 2.45,-2.325 2.412,-2.333 2.379,-2.354 2.358,-2.387 2.35,-2.425 2.35,-2.425 2.35,-2.65 2.343,-2.675 2.325,-2.693 2.3,-2.7 2.3,-2.7
  Top Layer region: -0.45,2.65 -0.437,2.7 -0.4,2.737 -0.35,2.75 -0.35,2.75 2.648,2.75 2.698,2.737 2.735,2.7 2.748,2.65 2.748,2.65 2.748,-0.325 2.735,-0.375 2.698,-0.412 2.648,-0.425 2.648,-0.425 1.95,-0.425 1.931,-0.429 1.915,-0.44 1.904,-0.456 1.9,-0.475 1.9,-0.475 1.9,-1.8 1.887,-1.85 1.85,-1.887 1.8,-1.9 1.8,-1.9 -0.35,-1.9 -0.4,-1.887 -0.437,-1.85 -0.45,-1.8 -0.45,-1.8
  silkscreen extent -3.37,-2.55 -0.72,2.55, body extent -2.5,-2.5 2.5,2.5, height 1
SMA [mm] "Molded Diode, 2-Leads, Body 4.3x2.6mm, IPC Medium Density, based on OnSemi component dimensions and land pattern"
  rect 2x2 smd: 1(-2,0) 2(2,0)
  silkscreen extent -3.66,-1.58 2.79,1.57, body extent -2.6,-1.3 2.6,1.3, height 2.42
SOD-123 [mm] "On Semi recommended land pattern"
  rect 0.915x1.22 smd: 1(-1.637,0) 2(1.637,0)
  silkscreen extent -2.74,-1.17 2.03,1.17, body extent -1.93,-0.9 1.93,0.9, height 1.35
SOP254P1020X230-4 [mm] "VISHAY"
  rect 1.3x0.9 smd: 1(-4.75,1.27) 2(-4.75,-1.27) 3(4.75,-1.27) 4(4.75,1.27)
  body extent -3.85,-2.05 3.85,2.05, height 2.02
WCAP-ATG5_D8H16 [mm] "Aluminum Electrolytic Capacitors, 8x16mm"
  rrect50% 1.3x1.3 hole 0.8: 1(1.75,0)
  round 1.3 hole 0.8: 2(-1.75,0)
  silkscreen extent -4.25,-4.25 4.25,4.25, body extent -3.99,-4 4,4, height 16.31
WCAP-CSSA_1808_L4.5W2H1.6 [mm] "Ceramic Capacitors, body 4.50x2.00mm"
  rect 1.05x2.3 smd: 1(-2.175,0) 2(2.175,0)
  silkscreen extent -1.3,-1.12 1.3,1.12, body extent -2.25,-1 2.25,1, height 1.6
WE-CMB_XS [mm] "WE-CMB Series Size XS"
  rect 1.5x1.5 hole 0.9: 1(-5,2.25)
  round 1.5 hole 0.9: 2(-5,-2.25) 3(5,-2.25) 4(5,2.25)
  silkscreen extent -6.5,-3.75 6.5,3.75, body extent -6.5,-3.75 6.5,3.75, height 16.24
WE-TI_5075 [mm] "Wurth WE-TI 5075"
  rect 1.4x1.4 hole 0.787: 1(-1.25,0)
  round 1.4 hole 0.787: 2(1.25,0)
  silkscreen extent -3,-3 3,3, body extent -3,-3 3,3, height 8.5
"X CAP small form 7_10_8" [mm]
  round 1.5 hole 1: 1(0,0) 2(7.5,0)
  silkscreen extent -1.27,-2.79 8.73,2.79

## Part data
C1: library part CMP-0112463-1, "WCAP-FTX2 Film Capacitor, THT, L13 x W8 x H14mm, 220nF, 275V", Capacitance Tolerance=+/-10%, Insulation Resistance=30000MOhm, Manufacturer="Wurth Elektronik", Operating Temperature Max=105°C, Operating Temperature Min=-40°C, Rate of Voltage Rise=300V/us, Rated Voltage (AC)=275V
C3: library part CMP-0008909-2, "CAP, CERM, 1000 pF, 630 V, +/- 10%, X7R, 1206", Cap_Case=1206, Manufacturer=MuRata, Supplier Part Number 1=490-3506-1-ND, TempCo=X7R, Tolerance_%=10%, Value1=Unknown, Value2=630V, ValueDisplayed=1000pF
C4: library part CMP-0008414-2, "CAP, CERM, 10 uF, 25 V, +/- 10%, X5R, 0805", Cap_Case=0805, Manufacturer="Taiyo Yuden", Supplier Part Number 1=587-2985-1-ND, TempCo=X5R, Tolerance_%=10%, Value1=Unknown, Value2=25V, ValueDisplayed=10uF
C6: library part CMP-0086497-1, "0.1µF ±10% 25V Ceramic Capacitor X8R 0603 (1608 Metric)", Manufacturer="TDK Corporation", TempCo=15%, Tolerance_%=10%
C8 C9 C64: library part CMP-0116785-1, "Aluminum Electrolytic Capacitor, Radial, THT, D8 x H20mm, 33µF, 400V", Capacitance Tolerance=+0%/-40%, Case/Size Code="D8 x H20mm", Leakage Current=264uA, Manufacturer=Yongming, Manufacturer Part Number=860021374027, Operating Temperature Max=105°C, Operating Temperature Min=-25°C, PartNumber=KCMD2002G330MF, Rated Voltage (DC)=400V, Ripple Current=200mA
C13: library part CMP-0007256-4, "CAP, CERM, 220 pF, 100 V, +/- 5%, C0G/NP0, 0603", Cap_Case=0603, Manufacturer=MuRata, Supplier Part Number 1=490-1359-1-ND, TempCo=C0G/NP0, Tolerance_%=5%, Value1=Unknown, Value2=100V, ValueDisplayed=220pF
C14: library part CMP-0076705-1, "CAP, CERM, 1 µF, 25 V,+/- 10%, X7R, AEC-Q200 Grade 1, 0603", Cap_Case=1.6x0.8x0.8mm, Manufacturer=TDK, Supplier Part Number 1=445-6931-1-ND, TempCo=X7R, Tolerance_%=10%, Value2=25V, ValueDisplayed=1µF
C15: library part CMP-0860569-1, "CAP, CERM, 10 µF, 25 V,+/- 10%, X5R, 0603", Cap_Case=0603, Manufacturer=MuRata, TempCo=X5R, Tolerance_%=10%, Value2=25V, ValueDisplayed=10µF
C16: library part CMP-0006687-2, "CAP, CERM, 330 pF, 50 V, +/- 10%, X7R, 0402", Cap_Case=0402, Manufacturer=MuRata, Supplier Part Number 1=490-3247-1-ND, TempCo=X7R, Tolerance_%=10%, Value1=Unknown, Value2=50V, ValueDisplayed=330pF
C17: library part CMP-0007040-4, "CAP, CERM, 1 µF, 25 V, +/- 10%, X7R, 0603", Cap_Case=0603, Manufacturer=TDK, Supplier Part Number 1=445-5956-1-ND, TempCo=X7R, Tolerance_%=10%, Value1=Unknown, Value2=25V, ValueDisplayed=1uF
C18: library part CMP-0006681-2, "CAP, CERM, 0.018 uF, 50 V, +/- 10%, X7R, 0402", Cap_Case=0402, Manufacturer=MuRata, Supplier Part Number 1=GRM155R71H183KA12D-ND, TempCo=X7R, Tolerance_%=10%, Value1=Unknown, Value2=50V, ValueDisplayed=0.018uF
C19 C22: library part CMP-0008729-1, "CAP, CERM, 0.1 uF, 450 V, +/- 20%, X7T, 1206", Cap_Case=1206, Manufacturer=TDK, Supplier Part Number 1=445-14838-1-ND, TempCo=X7T, Tolerance_%=20%, Value1=Unknown, Value2=450V, ValueDisplayed=0.1uF
C20: library part CMP-0006692-2, "CAP, CERM, 4700 pF, 50 V, +/- 10%, X7R, 0402", Cap_Case=0402, Manufacturer=MuRata, Supplier Part Number 1=490-1308-1-ND, TempCo=X7R, Tolerance_%=10%, Value1=Unknown, Value2=50V, ValueDisplayed=4700pF
C21 C222: library part CMP-0006230-2, "CAP, CERM, 100 pF, 50 V, +/- 10%, X7R, 0402", Cap_Case=0402, Manufacturer="Wurth Elektronik", Supplier Part Number 1=732-7550-1-ND, TempCo=X7R, Tolerance_%=10%, Value1=Unknown, Value2=50V, ValueDisplayed=100pF
C24 C25: library part CMP-0115938-1, "WCAP-CSSA Multilayer Ceramic Chip Safety Capacitor, size 1808, X7R Class II, 470pF, 250VAC", Capacitance Tolerance=+/-10%, Case/Size Code=1808, Impulse Voltage=2500VDC, Insulation Resistance=10GOhm, Manufacturer="Wurth Elektronik", Operating Temperature Max=125°C, Operating Temperature Min=-55°C, Rated Voltage (AC)=250V
D1: library part CMP-0120719-1, "Bridge Rectifier Single Phase Standard 600 V Surface Mount Z4-D", Digikey Part Number=641-1502-1-ND, Forward Current=4A, Manufacturer=Comchip, Max Surge Forward Current=150A, Mouser Part Number=750-Z4DGP406L-HF, Operating Temperature Range="-55°C to +175°C", Peak Reverse Current=0.08uA, ValueDisplayed=45pF
D3: library part CMP-0077082-2, "Diode, Standard Recovery Rectifier, 1000 V, 1 A, AEC-Q101, SMA", Manufacturer="ON Semiconductor", Value1=1A, Value2=1.1V
D4 D5: library part CMP-0029032-2, "Diode, Switching, 600 V, 1 A, SOD-123", Manufacturer="ON Semiconductor", Supplier Part Number 1=ES1JFLDKR-ND, Value1=1A, Value2=1V
EC6 EC7: "25V/470uF D5.5*11mm", Manufacturer=Yongming, PartNumber=NPXC1001E471MJTM, Voltage=25V
F1 F3: library part CMP-0003605-1, "Fuse, 3 A, 125VAC/VDC, SMD", Irating_A=3A, Manufacturer="Bel Fuse", Supplier Part Number 1=507-1050-1-ND
L1: library part CMP-0064517-1, "Inductor, Unshielded Drum Core, Ferrite, 22 uH, 1.7 A, 0.102 ohm, TH", Manufacturer="Wurth Elektronik", PartNumber=MCD-0608-220K-UL, Supplier Part Number 1=732-2570-ND, Value1="0.102 ohm", Value2=1.7A, ValueDisplayed=22uH
L2: library part CMP-0088773-1, "7*5", Manufacturer="Wurth Electronics", Operating Temperature Range="-40°C to +125°C", Part Number=7448201036010, Test Frequency=10kHz, Tolerance_%=30%
L5: library part CMP-0013113-2, "Coupled inductor, 1 mH, 2 A, 0.045 ohm, TH", Manufacturer="Wurth Elektronik", Supplier Part Number 1=732-1435-ND, ValueDisplayed=1mH
NT1: library part CMP-0078142-6, "Single point connection between nets.", Manufacturer=N/A
Q1: library part CMP-0001046-2, "MOSFET, N-CH, 150 V, 87 A, PG-TDSON-8", Alternate Manufacturer=None, Manufacturer="Infineon Technologies", Supplier Part Number 1=BSC093N15NS5ATMA1CT-ND, Value2="33 nC"
R1: library part CMP-0020554-3, "RES, 470 k, 5%, 0.125 W, AEC-Q200 Grade 0, 0805", Manufacturer=Vishay-Dale, Power_W=125mW, Supplier Part Number 1=541-470KACT-ND, TempCo="200 ppm/C", Tolerance_%=5%, Value2=0.125W, Value_Code=470k
R2 R9 R12: library part CMP-0001606-1, "RES Thick Film, 0Ω, 0.2W, 0402", Digikey Part Number=541-0.0YBCT-ND, Manufacturer="Vishay Dale", Mouser Part Number=71-CRCW04020000Z0EDH, Operating Temperature Range="-55°C to +155°C", Power_W=200mW
R3 R17: library part CMP-0018196-2, "RES, 30.0, 1%, 0.25 W, 1206", Manufacturer="Yageo America", Power_W=250mW, Supplier Part Number 1=311-30.0FRCT-ND, TempCo="100 ppm/C", Tolerance_%=1%, Value2=0.25W, Value_Code=30R0, ValueDisplayed=30.0
R4: library part CMP-0023013-5, "RES, 300, 1%, 0.1 W, 0603", Manufacturer=Yageo, Power_W=100mW, Supplier Part Number 1=311-300HRCT-ND, TempCo="100 ppm/C", Tolerance_%=1%, Value2=0.1W, Value_Code=300R, ValueDisplayed=300
R5: library part CMP-0018689-2, "RES, 4.7 k, 5%, 0.25 W, 1206", Manufacturer=Vishay-Dale, Power_W=250mW, Supplier Part Number 1=541-4.7KECT-ND, TempCo="200 ppm/C", Tolerance_%=5%, Value2=0.25W, Value_Code=4k70, ValueDisplayed=4.7k
R6: library part CMP-0022438-1, "RES, 47.0 k, 1%, 0.1 W, AEC-Q200 Grade 0, 0603", Manufacturer=Vishay-Dale, Power_W=100mW, Supplier Part Number 1=541-47.0KHCT-ND, TempCo="100 ppm/C", Tolerance_%=1%, Value2=0.1W, Value_Code=47k0, ValueDisplayed=47.0k
R7 R8: library part CMP-0026220-2, "RES, 28.7 k, 1%, 0.063 W, AEC-Q200 Grade 0, 0402", Manufacturer=Vishay-Dale, Power_W=63mW, Supplier Part Number 1=541-28.7KLCT-ND, TempCo="100 ppm/C", Tolerance_%=1%, Value2=0.063W, Value_Code=28k7, ValueDisplayed=28.7k
R10: library part CMP-0026329-2, "RES, 3.01 k, 1%, 0.063 W, AEC-Q200 Grade 0, 0402", Manufacturer=Vishay-Dale, Power_W=63mW, Supplier Part Number 1=541-3.01KLCT-ND, TempCo="100 ppm/C", Tolerance_%=1%, Value2=0.063W, Value_Code=3k01, ValueDisplayed=3.01k
R11: library part CMP-0022929-1, "RES, 232 k, 1%, 0.1 W, 0603", Manufacturer="Yageo America", Power_W=100mW, Supplier Part Number 1=311-232KHRCT-ND, TempCo="200 ppm/C", Tolerance_%=1%, Value2=0.1W, Value_Code=232k
R13: library part CMP-0026022-3, "RES, 150, 1%, 0.063 W, AEC-Q200 Grade 0, 0402", Manufacturer=Vishay-Dale, Power_W=63mW, Supplier Part Number 1=541-150LCT-ND, TempCo="100 ppm/C", Tolerance_%=1%, Value2=0.063W, Value_Code=150R, ValueDisplayed=150
R14: library part CMP-0026027-3, "RES, 15.0 k, 1%, 0.063 W, AEC-Q200 Grade 0, 0402", Manufacturer=Vishay-Dale, Power_W=63mW, Supplier Part Number 1=541-15.0KLCT-ND, TempCo="100 ppm/C", Tolerance_%=1%, Value2=0.063W, Value_Code=15k0, ValueDisplayed=15.0k
R15: library part CMP-0026739-1, "RES, 4.70 k, 1%, 0.0625 W, 0402", Manufacturer="Yageo America", Power_W=62.5mW, Supplier Part Number 1=311-4.7KLRCT-ND, TempCo="100 ppm/C", Tolerance_%=1%, Value2=0.0625W, Value_Code=4k70, ValueDisplayed=4.70k
R16: library part CMP-0026866-2, "RES, 1.0, 5%, 0.063 W, 0402", Manufacturer=Vishay-Dale, Power_W=63mW, Supplier Part Number 1=541-1.0JCT-ND, TempCo="200 ppm/C", Tolerance_%=5%, Value2=0.063W, Value_Code=1R00, ValueDisplayed=1.0
R19: library part CMP-0022338-2, "RES, 33.0 k, 1%, 0.1 W, 0603", Manufacturer=Vishay-Dale, Power_W=100mW, Supplier Part Number 1=541-33.0KHCT-ND, TempCo="100 ppm/C", Tolerance_%=1%, Value2=0.1W, Value_Code=33k0, ValueDisplayed=33.0k
R21: library part CMP-0027008-4, "RES, 0, 5%, 0.05 W, 0201", Manufacturer=Vishay-Dale, Power_W=50mW, Supplier Part Number 1=72M6743, TempCo=ppm/C, Tolerance_%=5%, Value2=0.05W, Value_Code=0000, ValueDisplayed=0
R42: library part CMP-0026543-1, "RES, 75.0 k, 1%, 0.063 W, 0402", Manufacturer=Vishay-Dale, Power_W=63mW, Supplier Part Number 1=541-75.0KLCT-ND, TempCo="100 ppm/C", Tolerance_%=1%, Value2=0.063W, Value_Code=75k0, ValueDisplayed=75.0k
R43: library part CMP-0026464-2, "RES, 5.23 k, 1%, 0.063 W, AEC-Q200 Grade 0, 0402", Manufacturer=Vishay-Dale, Power_W=63mW, Supplier Part Number 1=541-5.23KLCT-ND, TempCo="100 ppm/C", Tolerance_%=1%, Value2=0.063W, Value_Code=5k23, ValueDisplayed=5.23k
R50: library part CMP-0025712-2, "RES, 12, 5%, 0.1 W, 0603", Manufacturer=Vishay-Dale, Power_W=100mW, Supplier Part Number 1=541-12GCT-ND, TempCo="200 ppm/C", Tolerance_%=5%, Value2=0.1W, Value_Code=12R0, ValueDisplayed=12
RT1: library part CMP-0002353-2, "Thermistor NTC, 100k ohm, 1%, 0402", Manufacturer=MuRata, Power_W=100mW, Tolerance_%=1%
T1: Manufacturer="Fort Electronics", PartNumber=ATQ23-14
U1: library part CMP-0086802-1, "FAST TURN-OFF INTELLIGENT RECTIF", Manufacturer="Monolithic Power Systems"
U2: library part CMP-0066199-1, "2.5V Low Iq Adjustable Precision Shunt Regulator, DBZ0003A (SOT-23-3)", Alternate Manufacturer="Texas Instruments"
U3: library part CMP-0006160-3, "Optocoupler, 5 kV, 63-125% CTR, SMT", Manufacturer=Vishay-Semiconductor, Supplier Part Number 1=VOL618A-2TCT-ND, Voltage_Isolation_Vrms=5kV
U8: library part CMP-0122264-1, Manufacturer="Texas Instruments", Operating Temperature Range=to

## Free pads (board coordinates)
  round 1.5 hole 1.1: 1(-2.955,-25.185) 1(2.205,-25.245)
  oval 2.2x2.4 hole 1.7: 5(-44.85,10.14) 5(-44.82,13.545)
  round 1.524 hole 0.762: 8(-9.09,9.645) 8(-8.226,16.463) 9(-37.995,15.9) 9(-37.95,12.825) 9(-5.775,-25.155) 10(-5.88,-20.175)
  rect 1.2x1.8 smd far side: N(-37.475,15.545) N(-37.455,12.892) N(-35.08,12.88) N(-35.065,15.535)
  rect 2.5x1.2 smd far side: N(-4.575,2.145) N(-0.015,2.115)
  rect 2x2 smd: N(-4.32,-3.075) N(0.33,-3.12)
  rect 2x2 smd far side: N(-4.26,-3.09) N(0.315,-3.12)

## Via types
v1: diameter 0.5, hole 0.25, Top Layer to Bottom Layer, 301 vias
v2: diameter 0.5, hole 0.25, Top Layer to Bottom Layer, tented both sides, 45 vias
v3: diameter 0.61, hole 0.203, Top Layer to Bottom Layer, tented both sides, 16 vias
v4: diameter 0.5, hole 0.3, Top Layer to Bottom Layer, tented both sides, 15 vias
v5: diameter 0.5, hole 0.2, Top Layer to Bottom Layer, tented both sides, 12 vias

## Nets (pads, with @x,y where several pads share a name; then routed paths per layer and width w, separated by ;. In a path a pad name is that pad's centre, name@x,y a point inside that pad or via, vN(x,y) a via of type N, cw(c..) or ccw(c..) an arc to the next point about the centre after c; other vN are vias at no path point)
APGND: C16.2 NT1.2 R7.1 R8.1 R42.1 R43.1 RT1.1 U3.3 U8.10 | length 2
  Bottom Layer w0.254: U3.3@-24.905,25.41 -23.012,25.41 R42.1@-22.93,25.328
FB_ACDC: pad.N@-35.065,15.535 R2.1 R16.2 | length 17.7
  Top Layer w0.254: v3(-43.35,20.55) -43.278,20.55 -42.558,21.27 v3@-35.085,21.27 ; v4(-36.073,24.027) -36.073,22.258 v3@-35.085,21.27 ; v4(-35.008,20.622) -35.024,20.638 -35.024,21.209 v3(-35.04,21.225) v3@-35.085,21.27
  Bottom Layer w0.254: pad.N@-35.04,15.33 v4@-35.04,20.622
LINE: 
NetC1_1: 
NetC1_2: 
NetC3_1: C3.1 R1.1 R3.2 R17.2 | length 6.7
  Bottom Layer w0.8: R3.2@-26.401,11.339 -26.393,11.347 -24.298,11.347 -24.273,11.322 -22.283,11.322 -22.221,11.26 C3.1@-21.758,11.26 -21.752,11.255 -21.752,9.207 R1.1@-21.747,9.201
NetC3_2: C3.2 C9.1 C19.1 C22.1 C64.1 L1.2 R1.2 R5.2 T1.3 | length 44.2
  Top Layer w0.4: v3(-23.825,8.97) -23.785,9.01 -22.96,9.01 -22.205,9.765 -22.205,12.465 -20.94,13.73 -19.915,13.73 T1.3@-19.685,13.96
  Top Layer w1: C9.1@-14.913,14.699 -12.469,12.255 -5.84,12.255 -4.145,13.95 -4.145,21.139 -3.559,21.725 -0.801,21.725 L1.2@-0.725,21.801
  Top Layer w1.2: C64.1@-14.885,6.047 C9.1@-14.885,14.671
  Bottom Layer w0.5: L1.2@-0.725,21.801 -0.674,21.852 1.082,21.852 R5.2@1.133,21.902
  Bottom Layer w1.2: C3.2@-21.758,14.16 -19.608,14.16 -19.408,13.96 T1.3@-19.3,13.96
NetC8_1: C8.1 D1.1 L1.1 R5.1 | length 13.8
  Top Layer w1: C8.1@-6.361,22.464 -6.241,22.464 -5.384,23.321 -1.944,23.321 -1.164,24.101 -0.925,24.101 L1.1@-0.725,24.301
  Bottom Layer w0.5: L1.1@-0.725,24.301 -0.474,24.552 0.882,24.552 R5.1@1.133,24.802
  Bottom Layer w1: C8.1@-6.225,21.66 -6.225,19.74 -5.48,18.995 -5.48,17.505 D1.1@-4.83,16.855
NetC13_2: C13.2 R50.2 | length 0.9
  Bottom Layer w0.5: C13.2@-41.25,10.125 -41.242,10.132 -40.407,10.132 R50.2@-40.4,10.14
NetC14_1: C14.1 U1.4 | length 1.3
  Bottom Layer w0.254: C14.1@-38.009,1.223 -37.886,1.1 -37.886,1.058 -37.882,1.055 U1.4@-36.798,1.055
NetC15_1: C15.1 U8.11 | length 2
  Bottom Layer w0.254: U8.11@-19.198,23.13 -19.197,23.774 C15.1@-18.26,24.712
NetC16_1: C16.1 R12.1 U8.5 | length 5.1
  Top Layer w0.254: v3(-24.361,20.94) -24.29,20.94 -24.035,21.195 -22.021,21.195 v3(-21.961,21.255)
  Bottom Layer w0.254: R12.1@-25.108,20.932 -25.103,20.936 -24.366,20.936 v3(-24.361,20.94) ; C16.1@-22.51,21.186 -22.476,21.22 -21.996,21.22 v3(-21.961,21.255) -21.893,21.323 -21.525,21.323 -21.345,21.503 U8.5@-20.848,21.505 U8.5@-20.848,21.505
NetC17_2: C17.2 C18.1 R9.1 R10.2 R11.2 | length 5.7
  Bottom Layer w0.254: R11.2@-40.515,20.155 -40.29,19.93 -40.29,19.164 C17.2@-40.29,18.87 ; C17.2@-40.29,19.037 -40.163,19.164 -39.396,19.164 R9.1@-38.865,19.695 -38.475,19.305 -37.83,19.305 -37.71,19.185 -36.57,19.185 C18.1@-36.48,19.275
NetC18_2: C18.2 R13.2 | length 1.4
  Bottom Layer w0.254: R13.2@-36.795,21.78 -36.773,21.78 -36.6,21.607 -36.6,20.595 C18.2@-36.48,20.475
NetC20_1: C20.1 R15.1 | length 1.3
  Bottom Layer w0.254: C20.1@-39.525,23.67 -39.45,23.595 -39.45,22.53 R15.1@-39.345,22.425
NetC20_2: C20.2 C21.2 C222.2 R2.2 R14.1 U2.1 U3.2 | length 7.9
  Bottom Layer w0.254: U2.1@-41.833,25.296 -41.743,25.296 -41.543,25.296 -41.163,24.917 -40.803,24.917 C21.2@-40.74,24.853 -40.539,24.853 -39.542,24.853 C20.2@-39.429,24.966 ; C20.2@-39.525,24.87 C20.2@-39.429,24.966 ; C222.2@-37.275,25.108 -38.242,25.108 -38.415,24.935 R14.1@-38.415,24.885 -38.496,24.966 C20.2@-39.429,24.966 ; C222.2@-37.273,25.11 R2.2@-36.075,25.11 -34.86,25.11 U3.2@-34.572,25.398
